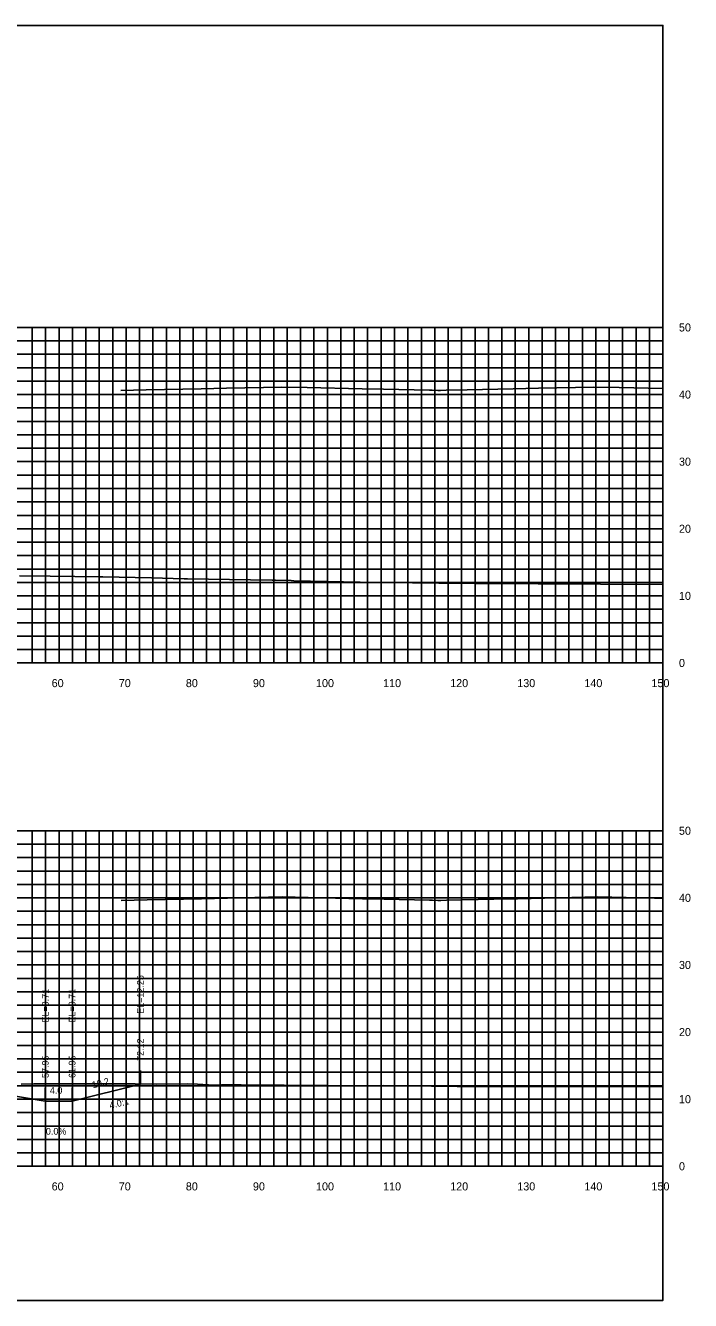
# Model space of a CAD drawing. Extents: x 1797714 to 1804825, y 249015 to 250269.
# Drawn here: x 1802659.2 to 1802758.3, y 249628.2 to 249818.2 of the extents above; entities that cross this region are included whole.
import ezdxf

# ---------------------------------------------------------------- set-up
doc = ezdxf.new("R2010")
doc.units = 0
for name, color, linetype in [('10', 7, 'Continuous'), ('3', 7, 'Continuous'), ('31', 7, 'Continuous'), ('4', 7, 'Continuous'), ('60', 7, 'Continuous'), ('CL-CNST', 7, 'Continuous'), ('Level 62', 7, 'Continuous'), ('M-ROADS', 7, 'Continuous')]:
    doc.layers.add(name, color=color, linetype=linetype)

msp = doc.modelspace()

# ---------------------------------------------------------------- linework, layer by layer
for p, q in [((1802676.28, 249660.42), (1802676.28, 249662.42)), ((1802662.11, 249657.88), (1802662.11, 249659.88)), ((1802666.11, 249657.88), (1802666.11, 249659.88))]:
    msp.add_line(p, q)
msp.add_lwpolyline([(1802454.16, 249628.17), (1802754.16, 249628.17), (1802754.16, 249818.17), (1802454.16, 249818.17)], close=True)
at = {"layer": '60'}
for p, q in [((1802754.16, 249723.17), (1802754.16, 249773.17)), ((1802754.22, 249773.17), (1802754.16, 249773.17)), ((1802754.22, 249763.17), (1802754.16, 249763.17)), ((1802754.22, 249753.17), (1802754.16, 249753.17)), ((1802754.22, 249743.17), (1802754.16, 249743.17)), ((1802754.22, 249733.17), (1802754.16, 249733.17)), ((1802454.16, 249723.17), (1802754.16, 249723.17)), ((1802664.16, 249723.11), (1802664.16, 249723.17)), ((1802674.16, 249723.11), (1802674.16, 249723.17)), ((1802684.16, 249723.11), (1802684.16, 249723.17)), ((1802694.16, 249723.11), (1802694.16, 249723.17)), ((1802704.16, 249723.11), (1802704.16, 249723.17)), ((1802714.16, 249723.11), (1802714.16, 249723.17)), ((1802724.16, 249723.11), (1802724.16, 249723.17)), ((1802734.16, 249723.11), (1802734.16, 249723.17)), ((1802744.16, 249723.11), (1802744.16, 249723.17)), ((1802754.16, 249723.11), (1802754.16, 249723.17)), ((1802754.22, 249723.17), (1802754.16, 249723.17)), ((1802754.16, 249648.17), (1802754.16, 249698.17)), ((1802754.22, 249698.17), (1802754.16, 249698.17)), ((1802754.22, 249688.17), (1802754.16, 249688.17)), ((1802754.22, 249678.17), (1802754.16, 249678.17)), ((1802754.22, 249668.17), (1802754.16, 249668.17)), ((1802754.22, 249658.17), (1802754.16, 249658.17)), ((1802454.16, 249648.17), (1802754.16, 249648.17)), ((1802664.16, 249648.11), (1802664.16, 249648.17)), ((1802674.16, 249648.11), (1802674.16, 249648.17)), ((1802684.16, 249648.11), (1802684.16, 249648.17)), ((1802694.16, 249648.11), (1802694.16, 249648.17)), ((1802704.16, 249648.11), (1802704.16, 249648.17)), ((1802714.16, 249648.11), (1802714.16, 249648.17)), ((1802724.16, 249648.11), (1802724.16, 249648.17)), ((1802734.16, 249648.11), (1802734.16, 249648.17)), ((1802744.16, 249648.11), (1802744.16, 249648.17)), ((1802754.16, 249648.11), (1802754.16, 249648.17)), ((1802754.22, 249648.17), (1802754.16, 249648.17))]:
    msp.add_line(p, q, dxfattribs=at)
at = {"layer": 'CL-CNST'}
for points in [[(1802673.36, 249763.77), (1802677.13, 249763.85), (1802685.36, 249764.03), (1802689.14, 249764.11), (1802697.36, 249764.29), (1802701.14, 249764.21), (1802709.36, 249764.03), (1802712.51, 249763.96), (1802719.36, 249763.81), (1802719.75, 249763.8), (1802720.61, 249763.78), (1802720.61, 249763.78), (1802720.61, 249763.78), (1802721, 249763.79), (1802721.86, 249763.81), (1802725.01, 249763.88), (1802731.86, 249764.03), (1802735.64, 249764.11), (1802743.86, 249764.29), (1802747.65, 249764.21), (1802754.16, 249764.07)], [(1802673.4, 249687.77), (1802677.27, 249687.85), (1802685.4, 249688.03), (1802689.27, 249688.12), (1802697.4, 249688.3), (1802701.27, 249688.21), (1802709.4, 249688.03), (1802712.63, 249687.96), (1802719.4, 249687.81), (1802719.81, 249687.8), (1802720.65, 249687.79), (1802720.65, 249687.78), (1802720.65, 249687.77), (1802721.06, 249687.78), (1802721.9, 249687.8), (1802728.99, 249687.96), (1802732.49, 249688.03), (1802740.61, 249688.21), (1802744.49, 249688.3), (1802752.92, 249688.11), (1802754.16, 249688.08)], [(1802582, 249661.74), (1802592, 249662.14), (1802604.16, 249662.37), (1802631.15, 249661.77), (1802635.15, 249661.61), (1802641.11, 249661.38), (1802662.11, 249657.88), (1802666.11, 249657.88), (1802676.28, 249660.42)]]:
    msp.add_lwpolyline(points, dxfattribs=at)
at = {"layer": 'Level 62'}
for p, q in [((1802454.16, 249773.17), (1802754.16, 249773.17)), ((1802660.16, 249723.17), (1802660.16, 249773.17)), ((1802662.16, 249723.17), (1802662.16, 249773.17)), ((1802664.16, 249723.17), (1802664.16, 249773.17)), ((1802666.16, 249723.17), (1802666.16, 249773.17)), ((1802668.16, 249723.17), (1802668.16, 249773.17)), ((1802670.16, 249723.17), (1802670.16, 249773.17)), ((1802672.16, 249723.17), (1802672.16, 249773.17)), ((1802674.16, 249723.17), (1802674.16, 249773.17)), ((1802676.16, 249723.17), (1802676.16, 249773.17)), ((1802678.16, 249723.17), (1802678.16, 249773.17)), ((1802680.16, 249723.17), (1802680.16, 249773.17)), ((1802682.16, 249723.17), (1802682.16, 249773.17)), ((1802684.16, 249723.17), (1802684.16, 249773.17)), ((1802686.16, 249723.17), (1802686.16, 249773.17)), ((1802688.16, 249723.17), (1802688.16, 249773.17)), ((1802690.16, 249723.17), (1802690.16, 249773.17)), ((1802692.16, 249723.17), (1802692.16, 249773.17)), ((1802694.16, 249723.17), (1802694.16, 249773.17)), ((1802696.16, 249723.17), (1802696.16, 249773.17)), ((1802698.16, 249723.17), (1802698.16, 249773.17)), ((1802700.16, 249723.17), (1802700.16, 249773.17)), ((1802702.16, 249723.17), (1802702.16, 249773.17)), ((1802704.16, 249723.17), (1802704.16, 249773.17)), ((1802706.16, 249723.17), (1802706.16, 249773.17)), ((1802708.16, 249723.17), (1802708.16, 249773.17)), ((1802710.16, 249723.17), (1802710.16, 249773.17)), ((1802712.16, 249723.17), (1802712.16, 249773.17)), ((1802714.16, 249723.17), (1802714.16, 249773.17)), ((1802716.16, 249723.17), (1802716.16, 249773.17)), ((1802718.16, 249723.17), (1802718.16, 249773.17)), ((1802720.16, 249723.17), (1802720.16, 249773.17)), ((1802722.16, 249723.17), (1802722.16, 249773.17)), ((1802724.16, 249723.17), (1802724.16, 249773.17)), ((1802726.16, 249723.17), (1802726.16, 249773.17)), ((1802728.16, 249723.17), (1802728.16, 249773.17)), ((1802730.16, 249723.17), (1802730.16, 249773.17)), ((1802732.16, 249723.17), (1802732.16, 249773.17)), ((1802734.16, 249723.17), (1802734.16, 249773.17)), ((1802736.16, 249723.17), (1802736.16, 249773.17)), ((1802738.16, 249723.17), (1802738.16, 249773.17)), ((1802740.16, 249723.17), (1802740.16, 249773.17)), ((1802742.16, 249723.17), (1802742.16, 249773.17)), ((1802744.16, 249723.17), (1802744.16, 249773.17)), ((1802746.16, 249723.17), (1802746.16, 249773.17)), ((1802748.16, 249723.17), (1802748.16, 249773.17)), ((1802750.16, 249723.17), (1802750.16, 249773.17)), ((1802752.16, 249723.17), (1802752.16, 249773.17)), ((1802754.16, 249723.17), (1802754.16, 249773.17)), ((1802454.16, 249771.17), (1802754.16, 249771.17)), ((1802454.16, 249769.17), (1802754.16, 249769.17)), ((1802454.16, 249767.17), (1802754.16, 249767.17)), ((1802454.16, 249765.17), (1802754.16, 249765.17)), ((1802454.16, 249763.17), (1802754.16, 249763.17)), ((1802454.16, 249761.17), (1802754.16, 249761.17)), ((1802454.16, 249759.17), (1802754.16, 249759.17)), ((1802454.16, 249757.17), (1802754.16, 249757.17)), ((1802454.16, 249755.17), (1802754.16, 249755.17)), ((1802454.16, 249753.17), (1802754.16, 249753.17)), ((1802454.16, 249751.17), (1802754.16, 249751.17)), ((1802454.16, 249749.17), (1802754.16, 249749.17)), ((1802454.16, 249747.17), (1802754.16, 249747.17)), ((1802454.16, 249745.17), (1802754.16, 249745.17)), ((1802454.16, 249743.17), (1802754.16, 249743.17)), ((1802454.16, 249741.17), (1802754.16, 249741.17)), ((1802454.16, 249739.17), (1802754.16, 249739.17)), ((1802454.16, 249737.17), (1802754.16, 249737.17)), ((1802454.16, 249735.17), (1802754.16, 249735.17)), ((1802454.16, 249733.17), (1802754.16, 249733.17)), ((1802454.16, 249731.17), (1802754.16, 249731.17)), ((1802454.16, 249729.17), (1802754.16, 249729.17)), ((1802454.16, 249727.17), (1802754.16, 249727.17)), ((1802454.16, 249725.17), (1802754.16, 249725.17)), ((1802454.16, 249723.17), (1802754.16, 249723.17)), ((1802454.16, 249698.17), (1802754.16, 249698.17)), ((1802660.16, 249648.17), (1802660.16, 249698.17)), ((1802662.16, 249648.17), (1802662.16, 249698.17)), ((1802664.16, 249648.17), (1802664.16, 249698.17)), ((1802666.16, 249648.17), (1802666.16, 249698.17)), ((1802668.16, 249648.17), (1802668.16, 249698.17)), ((1802670.16, 249648.17), (1802670.16, 249698.17)), ((1802672.16, 249648.17), (1802672.16, 249698.17)), ((1802674.16, 249648.17), (1802674.16, 249698.17)), ((1802676.16, 249648.17), (1802676.16, 249698.17)), ((1802678.16, 249648.17), (1802678.16, 249698.17)), ((1802680.16, 249648.17), (1802680.16, 249698.17)), ((1802682.16, 249648.17), (1802682.16, 249698.17)), ((1802684.16, 249648.17), (1802684.16, 249698.17)), ((1802686.16, 249648.17), (1802686.16, 249698.17)), ((1802688.16, 249648.17), (1802688.16, 249698.17)), ((1802690.16, 249648.17), (1802690.16, 249698.17)), ((1802692.16, 249648.17), (1802692.16, 249698.17)), ((1802694.16, 249648.17), (1802694.16, 249698.17)), ((1802696.16, 249648.17), (1802696.16, 249698.17)), ((1802698.16, 249648.17), (1802698.16, 249698.17)), ((1802700.16, 249648.17), (1802700.16, 249698.17)), ((1802702.16, 249648.17), (1802702.16, 249698.17)), ((1802704.16, 249648.17), (1802704.16, 249698.17)), ((1802706.16, 249648.17), (1802706.16, 249698.17)), ((1802708.16, 249648.17), (1802708.16, 249698.17)), ((1802710.16, 249648.17), (1802710.16, 249698.17)), ((1802712.16, 249648.17), (1802712.16, 249698.17)), ((1802714.16, 249648.17), (1802714.16, 249698.17)), ((1802716.16, 249648.17), (1802716.16, 249698.17)), ((1802718.16, 249648.17), (1802718.16, 249698.17)), ((1802720.16, 249648.17), (1802720.16, 249698.17)), ((1802722.16, 249648.17), (1802722.16, 249698.17)), ((1802724.16, 249648.17), (1802724.16, 249698.17)), ((1802726.16, 249648.17), (1802726.16, 249698.17)), ((1802728.16, 249648.17), (1802728.16, 249698.17)), ((1802730.16, 249648.17), (1802730.16, 249698.17)), ((1802732.16, 249648.17), (1802732.16, 249698.17)), ((1802734.16, 249648.17), (1802734.16, 249698.17)), ((1802736.16, 249648.17), (1802736.16, 249698.17)), ((1802738.16, 249648.17), (1802738.16, 249698.17)), ((1802740.16, 249648.17), (1802740.16, 249698.17)), ((1802742.16, 249648.17), (1802742.16, 249698.17)), ((1802744.16, 249648.17), (1802744.16, 249698.17)), ((1802746.16, 249648.17), (1802746.16, 249698.17)), ((1802748.16, 249648.17), (1802748.16, 249698.17)), ((1802750.16, 249648.17), (1802750.16, 249698.17)), ((1802752.16, 249648.17), (1802752.16, 249698.17)), ((1802754.16, 249648.17), (1802754.16, 249698.17)), ((1802454.16, 249696.17), (1802754.16, 249696.17)), ((1802454.16, 249694.17), (1802754.16, 249694.17)), ((1802454.16, 249692.17), (1802754.16, 249692.17)), ((1802454.16, 249690.17), (1802754.16, 249690.17)), ((1802454.16, 249688.17), (1802754.16, 249688.17)), ((1802454.16, 249686.17), (1802754.16, 249686.17)), ((1802454.16, 249684.17), (1802754.16, 249684.17)), ((1802454.16, 249682.17), (1802754.16, 249682.17)), ((1802454.16, 249680.17), (1802754.16, 249680.17)), ((1802454.16, 249678.17), (1802754.16, 249678.17)), ((1802454.16, 249676.17), (1802754.16, 249676.17)), ((1802454.16, 249674.17), (1802754.16, 249674.17)), ((1802454.16, 249672.17), (1802754.16, 249672.17)), ((1802454.16, 249670.17), (1802754.16, 249670.17)), ((1802454.16, 249668.17), (1802754.16, 249668.17)), ((1802454.16, 249666.17), (1802754.16, 249666.17)), ((1802454.16, 249664.17), (1802754.16, 249664.17)), ((1802454.16, 249662.17), (1802754.16, 249662.17)), ((1802454.16, 249660.17), (1802754.16, 249660.17)), ((1802454.16, 249658.17), (1802754.16, 249658.17)), ((1802454.16, 249656.17), (1802754.16, 249656.17)), ((1802454.16, 249654.17), (1802754.16, 249654.17)), ((1802454.16, 249652.17), (1802754.16, 249652.17)), ((1802454.16, 249650.17), (1802754.16, 249650.17)), ((1802454.16, 249648.17), (1802754.16, 249648.17))]:
    msp.add_line(p, q, dxfattribs=at)
at = {"layer": 'M-ROADS'}
for points in [[(1802658.26, 249736.16), (1802662.86, 249736.12), (1802670.17, 249736.02), (1802670.4, 249736.02), (1802670.67, 249736.02), (1802677.92, 249735.85), (1802682.79, 249735.71), (1802682.98, 249735.71), (1802683.3, 249735.71), (1802692.72, 249735.56), (1802695.91, 249735.49), (1802696.31, 249735.49), (1802696.41, 249735.49), (1802698.76, 249735.44), (1802699.16, 249735.43), (1802709.02, 249735.2), (1802720.75, 249735.08), (1802720.77, 249735.08), (1802721.05, 249735.08), (1802721.06, 249735.08), (1802721.55, 249735.08), (1802721.66, 249735.07), (1802721.67, 249735.07), (1802721.93, 249735.06), (1802726.29, 249735), (1802754.16, 249734.85)], [(1802658.5, 249660.4), (1802660.39, 249660.43), (1802660.64, 249660.44), (1802667.15, 249660.44), (1802670.18, 249660.46), (1802675.49, 249660.43), (1802678.69, 249660.38), (1802683.37, 249660.45), (1802684.79, 249660.38), (1802687.21, 249660.28), (1802688.39, 249660.29), (1802691.32, 249660.31), (1802704.17, 249660.23), (1802708.74, 249660.18), (1802709.19, 249660.18), (1802709.32, 249660.18), (1802709.93, 249660.18), (1802712.56, 249660.19), (1802719.66, 249660.11), (1802723.52, 249660.07), (1802725.01, 249660.08), (1802726.38, 249660.08), (1802726.67, 249660.08), (1802727.66, 249660.08), (1802728.85, 249660.05), (1802729.94, 249660.03), (1802741.85, 249660.04), (1802754.16, 249660.04)]]:
    msp.add_lwpolyline(points, dxfattribs=at)

# ---------------------------------------------------------------- texts
msp.add_text('4.0:1', height=1, rotation=14.0362).set_placement((1802671.8, 249656.72))
at = {"layer": '10'}
for s, p in [('60', (1802663.06, 249719.57)), ('70', (1802673.06, 249719.57)), ('80', (1802683.06, 249719.57)), ('90', (1802693.06, 249719.57)), ('100', (1802702.46, 249719.57)), ('110', (1802712.46, 249719.57)), ('120', (1802722.46, 249719.57)), ('130', (1802732.46, 249719.57)), ('140', (1802742.46, 249719.57)), ('150', (1802752.46, 249719.57)), ('60', (1802663.06, 249644.57)), ('70', (1802673.06, 249644.57)), ('80', (1802683.06, 249644.57)), ('90', (1802693.06, 249644.57)), ('100', (1802702.46, 249644.57)), ('110', (1802712.46, 249644.57)), ('120', (1802722.46, 249644.57)), ('130', (1802732.46, 249644.57)), ('140', (1802742.46, 249644.57)), ('150', (1802752.46, 249644.57))]:
    msp.add_text(s, height=1.2, dxfattribs=at).set_placement(p)
at = {"layer": '3'}
for s, p in [('EL=12.25', (1802676.78, 249670.89)), ('EL=9.71', (1802662.61, 249669.59)), ('EL=9.71', (1802666.61, 249669.59)), ('72.12', (1802676.78, 249663.87)), ('57.95', (1802662.61, 249661.33)), ('61.95', (1802666.61, 249661.33))]:
    msp.add_text(s, height=1, rotation=90, dxfattribs=at).set_placement(p)
at = {"layer": '31'}
for s, p in [('50', (1802756.56, 249772.57)), ('40', (1802756.56, 249762.57)), ('30', (1802756.56, 249752.57)), ('20', (1802756.56, 249742.57)), ('10', (1802756.56, 249732.57)), ('0', (1802756.56, 249722.57)), ('50', (1802756.56, 249697.57)), ('40', (1802756.56, 249687.57)), ('30', (1802756.56, 249677.57)), ('20', (1802756.56, 249667.57)), ('10', (1802756.56, 249657.57)), ('0', (1802756.56, 249647.57))]:
    msp.add_text(s, height=1.2, dxfattribs=at).set_placement(p)
at = {"layer": '4'}
msp.add_text('10.2', height=1, rotation=14.0362, dxfattribs=at).set_placement((1802669.2, 249659.78))
for s, p in [('4.0', (1802662.79, 249658.98)), ('0.0%', (1802662.2, 249652.88))]:
    msp.add_text(s, height=1, dxfattribs=at).set_placement(p)

doc.saveas('drawing.dxf')
